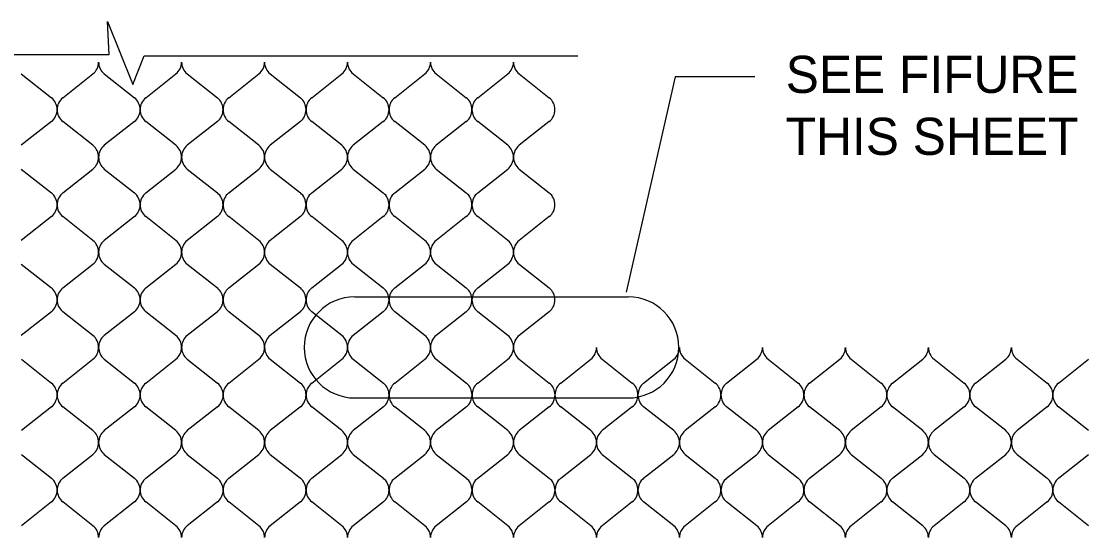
# Model space of a CAD drawing. Extents: x 638850 to 644908, y 297188 to 298900.
# Drawn here: x 640795.8 to 640882, y 298180.3 to 298222 of the extents above; entities that cross this region are included whole.
import ezdxf

# ---------------------------------------------------------------- set-up
doc = ezdxf.new("R2010")
doc.units = 0
for name, color, linetype in [('1', 7, 'Continuous'), ('2', 7, 'Continuous'), ('7', 7, 'Continuous')]:
    doc.layers.add(name, color=color, linetype=linetype)

msp = doc.modelspace()

# ---------------------------------------------------------------- linework, layer by layer
at = {"layer": '1'}
msp.add_line((640848.571, 298217.514), (640844.631, 298200.118), dxfattribs=at)
msp.add_lwpolyline([(640802.892, 298219.299), (640802.756, 298221.985), (640804.794, 298216.888), (640805.72, 298219.205)], dxfattribs=at)
for centre, start, end in [((640822.714, 298195.671), 90, 270), ((640844.797, 298195.671), 270, 90)]:
    msp.add_arc(centre, 4.078, start, end, dxfattribs=at)
at = {"layer": '2'}
for p, q in [((640795.796, 298217.737), (640798.228, 298215.819)), ((640799.147, 298215.819), (640801.579, 298217.737)), ((640802.497, 298217.737), (640804.929, 298215.819)), ((640805.845, 298215.819), (640808.277, 298217.737)), ((640809.195, 298217.737), (640811.627, 298215.819)), ((640812.541, 298215.819), (640814.973, 298217.737)), ((640815.891, 298217.737), (640818.323, 298215.819)), ((640819.239, 298215.819), (640821.671, 298217.737)), ((640822.589, 298217.737), (640825.021, 298215.819)), ((640825.94, 298215.819), (640828.372, 298217.737)), ((640829.29, 298217.737), (640831.722, 298215.819)), ((640832.638, 298215.819), (640835.07, 298217.737)), ((640835.988, 298217.737), (640838.42, 298215.819)), ((640798.228, 298213.899), (640795.796, 298211.98)), ((640801.579, 298211.98), (640799.147, 298213.899)), ((640804.929, 298213.899), (640802.497, 298211.98)), ((640808.277, 298211.98), (640805.845, 298213.899)), ((640811.627, 298213.899), (640809.195, 298211.98)), ((640814.973, 298211.98), (640812.541, 298213.899)), ((640818.323, 298213.899), (640815.891, 298211.98)), ((640821.671, 298211.98), (640819.239, 298213.899)), ((640825.021, 298213.899), (640822.589, 298211.98)), ((640828.372, 298211.98), (640825.94, 298213.899)), ((640831.722, 298213.899), (640829.29, 298211.98)), ((640835.07, 298211.98), (640832.638, 298213.899)), ((640838.42, 298213.899), (640835.988, 298211.98)), ((640795.796, 298210.062), (640798.228, 298208.144)), ((640799.147, 298208.144), (640801.579, 298210.062)), ((640802.497, 298210.062), (640804.929, 298208.144)), ((640805.845, 298208.144), (640808.277, 298210.062)), ((640809.195, 298210.062), (640811.627, 298208.144)), ((640812.541, 298208.144), (640814.973, 298210.062)), ((640815.891, 298210.062), (640818.323, 298208.144)), ((640819.239, 298208.144), (640821.671, 298210.062)), ((640822.589, 298210.062), (640825.021, 298208.144)), ((640825.94, 298208.144), (640828.372, 298210.062)), ((640829.29, 298210.062), (640831.722, 298208.144)), ((640832.638, 298208.144), (640835.07, 298210.062)), ((640835.988, 298210.062), (640838.42, 298208.144)), ((640798.228, 298206.224), (640795.796, 298204.306)), ((640801.579, 298204.306), (640799.147, 298206.224)), ((640804.929, 298206.224), (640802.497, 298204.306)), ((640808.277, 298204.306), (640805.845, 298206.224)), ((640811.627, 298206.224), (640809.195, 298204.306)), ((640814.973, 298204.306), (640812.541, 298206.224)), ((640818.323, 298206.224), (640815.891, 298204.306)), ((640821.671, 298204.306), (640819.239, 298206.224)), ((640825.021, 298206.224), (640822.589, 298204.306)), ((640828.372, 298204.306), (640825.94, 298206.224)), ((640831.722, 298206.224), (640829.29, 298204.306)), ((640835.07, 298204.306), (640832.638, 298206.224)), ((640838.42, 298206.224), (640835.988, 298204.306)), ((640795.796, 298202.388), (640798.228, 298200.469)), ((640799.147, 298200.469), (640801.579, 298202.388)), ((640802.497, 298202.388), (640804.929, 298200.469)), ((640805.845, 298200.469), (640808.277, 298202.388)), ((640809.195, 298202.388), (640811.627, 298200.469)), ((640812.541, 298200.469), (640814.973, 298202.388)), ((640815.891, 298202.388), (640818.323, 298200.469)), ((640819.239, 298200.469), (640821.671, 298202.388)), ((640822.589, 298202.388), (640825.021, 298200.469)), ((640825.94, 298200.469), (640828.372, 298202.388)), ((640829.29, 298202.388), (640831.722, 298200.469)), ((640832.638, 298200.469), (640835.07, 298202.388)), ((640835.988, 298202.388), (640838.42, 298200.469)), ((640798.228, 298198.549), (640795.796, 298196.631)), ((640801.579, 298196.631), (640799.147, 298198.549)), ((640804.929, 298198.549), (640802.497, 298196.631)), ((640808.277, 298196.631), (640805.845, 298198.549)), ((640811.627, 298198.549), (640809.195, 298196.631)), ((640814.973, 298196.631), (640812.541, 298198.549)), ((640818.323, 298198.549), (640815.891, 298196.631)), ((640821.671, 298196.631), (640819.239, 298198.549)), ((640825.021, 298198.549), (640822.589, 298196.631)), ((640828.372, 298196.631), (640825.94, 298198.549)), ((640831.722, 298198.549), (640829.29, 298196.631)), ((640835.07, 298196.631), (640832.638, 298198.549)), ((640838.42, 298198.549), (640835.988, 298196.631)), ((640795.801, 298194.711), (640798.233, 298192.792)), ((640799.149, 298192.792), (640801.581, 298194.711)), ((640802.499, 298194.711), (640804.931, 298192.792)), ((640805.847, 298192.792), (640808.279, 298194.711)), ((640809.197, 298194.711), (640811.629, 298192.792)), ((640812.545, 298192.792), (640814.978, 298194.711)), ((640815.895, 298194.711), (640818.327, 298192.792)), ((640819.244, 298192.792), (640821.676, 298194.711)), ((640822.594, 298194.711), (640825.026, 298192.792)), ((640825.942, 298192.792), (640828.374, 298194.711)), ((640829.292, 298194.711), (640831.724, 298192.792)), ((640832.64, 298192.792), (640835.072, 298194.711)), ((640835.99, 298194.711), (640838.422, 298192.792)), ((640839.338, 298192.792), (640841.771, 298194.711)), ((640842.688, 298194.711), (640845.12, 298192.792)), ((640846.037, 298192.792), (640848.469, 298194.711)), ((640849.387, 298194.711), (640851.819, 298192.792)), ((640852.735, 298192.792), (640855.167, 298194.711)), ((640856.085, 298194.711), (640858.517, 298192.792)), ((640859.433, 298192.792), (640861.865, 298194.711)), ((640862.783, 298194.711), (640865.215, 298192.792)), ((640866.131, 298192.792), (640868.564, 298194.711)), ((640869.481, 298194.711), (640871.913, 298192.792)), ((640872.83, 298192.792), (640875.262, 298194.711)), ((640876.18, 298194.711), (640878.612, 298192.792)), ((640879.528, 298192.792), (640881.96, 298194.711)), ((640798.233, 298190.872), (640795.801, 298188.954)), ((640801.581, 298188.954), (640799.149, 298190.872)), ((640804.931, 298190.872), (640802.499, 298188.954)), ((640808.279, 298188.954), (640805.847, 298190.872)), ((640811.629, 298190.872), (640809.197, 298188.954)), ((640814.978, 298188.954), (640812.545, 298190.872)), ((640818.327, 298190.872), (640815.895, 298188.954)), ((640821.676, 298188.954), (640819.244, 298190.872)), ((640825.026, 298190.872), (640822.594, 298188.954)), ((640828.374, 298188.954), (640825.942, 298190.872)), ((640831.724, 298190.872), (640829.292, 298188.954)), ((640835.072, 298188.954), (640832.64, 298190.872)), ((640838.422, 298190.872), (640835.99, 298188.954)), ((640841.771, 298188.954), (640839.338, 298190.872)), ((640845.12, 298190.872), (640842.688, 298188.954)), ((640848.469, 298188.954), (640846.037, 298190.872)), ((640851.819, 298190.872), (640849.387, 298188.954)), ((640855.167, 298188.954), (640852.735, 298190.872)), ((640858.517, 298190.872), (640856.085, 298188.954)), ((640861.865, 298188.954), (640859.433, 298190.872)), ((640865.215, 298190.872), (640862.783, 298188.954)), ((640868.564, 298188.954), (640866.131, 298190.872)), ((640871.913, 298190.872), (640869.481, 298188.954)), ((640875.262, 298188.954), (640872.83, 298190.872)), ((640878.612, 298190.872), (640876.18, 298188.954)), ((640881.96, 298188.954), (640879.528, 298190.872)), ((640795.801, 298187.034), (640798.233, 298185.115)), ((640799.149, 298185.115), (640801.581, 298187.034)), ((640802.499, 298187.034), (640804.931, 298185.115)), ((640805.847, 298185.115), (640808.279, 298187.034)), ((640809.197, 298187.034), (640811.629, 298185.115)), ((640812.545, 298185.115), (640814.978, 298187.034)), ((640815.895, 298187.034), (640818.327, 298185.115)), ((640819.244, 298185.115), (640821.676, 298187.034)), ((640822.594, 298187.034), (640825.026, 298185.115)), ((640825.942, 298185.115), (640828.374, 298187.034)), ((640829.292, 298187.034), (640831.724, 298185.115)), ((640832.64, 298185.115), (640835.072, 298187.034)), ((640835.99, 298187.034), (640838.422, 298185.115)), ((640839.338, 298185.115), (640841.771, 298187.034)), ((640842.688, 298187.034), (640845.12, 298185.115)), ((640846.037, 298185.115), (640848.469, 298187.034)), ((640849.387, 298187.034), (640851.819, 298185.115)), ((640852.735, 298185.115), (640855.167, 298187.034)), ((640856.085, 298187.034), (640858.517, 298185.115)), ((640859.433, 298185.115), (640861.865, 298187.034)), ((640862.783, 298187.034), (640865.215, 298185.115)), ((640866.131, 298185.115), (640868.564, 298187.034)), ((640869.481, 298187.034), (640871.913, 298185.115)), ((640872.83, 298185.115), (640875.262, 298187.034)), ((640876.18, 298187.034), (640878.612, 298185.115)), ((640879.528, 298185.115), (640881.96, 298187.034)), ((640798.233, 298183.195), (640795.801, 298181.277)), ((640801.581, 298181.277), (640799.149, 298183.195)), ((640804.931, 298183.195), (640802.499, 298181.277)), ((640808.279, 298181.277), (640805.847, 298183.195)), ((640811.629, 298183.195), (640809.197, 298181.277)), ((640814.978, 298181.277), (640812.545, 298183.195)), ((640818.327, 298183.195), (640815.895, 298181.277)), ((640821.676, 298181.277), (640819.244, 298183.195)), ((640825.026, 298183.195), (640822.594, 298181.277)), ((640828.374, 298181.277), (640825.942, 298183.195)), ((640831.724, 298183.195), (640829.292, 298181.277)), ((640835.072, 298181.277), (640832.64, 298183.195)), ((640838.422, 298183.195), (640835.99, 298181.277)), ((640841.771, 298181.277), (640839.338, 298183.195)), ((640845.12, 298183.195), (640842.688, 298181.277)), ((640848.469, 298181.277), (640846.037, 298183.195)), ((640851.819, 298183.195), (640849.387, 298181.277)), ((640855.167, 298181.277), (640852.735, 298183.195)), ((640858.517, 298183.195), (640856.085, 298181.277)), ((640861.865, 298181.277), (640859.433, 298183.195)), ((640865.215, 298183.195), (640862.783, 298181.277)), ((640868.564, 298181.277), (640866.131, 298183.195)), ((640871.913, 298183.195), (640869.481, 298181.277)), ((640875.262, 298181.277), (640872.83, 298183.195)), ((640878.612, 298183.195), (640876.18, 298181.277)), ((640881.96, 298181.277), (640879.528, 298183.195))]:
    msp.add_line(p, q, dxfattribs=at)
for centre, start, end in [((640800.803, 298218.697), 308.94823, 0), ((640803.272, 298218.697), 180, 231.05177), ((640807.501, 298218.697), 308.94823, 0), ((640809.971, 298218.697), 180, 231.05177), ((640814.197, 298218.697), 308.94823, 0), ((640816.667, 298218.697), 180, 231.05177), ((640820.895, 298218.697), 308.94823, 0), ((640823.365, 298218.697), 180, 231.05177), ((640827.596, 298218.697), 308.94823, 0), ((640830.065, 298218.697), 180, 231.05177), ((640834.294, 298218.697), 308.94823, 0), ((640836.764, 298218.697), 180, 231.05177), ((640797.452, 298214.859), 0, 51.05177), ((640799.923, 298214.859), 128.94823, 180), ((640804.152, 298214.859), 0, 51.05177), ((640806.622, 298214.859), 128.94823, 180), ((640810.85, 298214.859), 0, 51.05177), ((640813.318, 298214.859), 128.94823, 180), ((640817.546, 298214.859), 0, 51.05177), ((640820.016, 298214.859), 128.94823, 180), ((640824.245, 298214.859), 0, 51.05177), ((640826.716, 298214.859), 128.94823, 180), ((640830.945, 298214.859), 0, 51.05177), ((640833.415, 298214.859), 128.94823, 180), ((640837.643, 298214.859), 0, 51.05177), ((640797.452, 298214.859), 308.94823, 0), ((640799.923, 298214.859), 180, 231.05177), ((640804.152, 298214.859), 308.94823, 0), ((640806.622, 298214.859), 180, 231.05177), ((640810.85, 298214.859), 308.94823, 0), ((640813.318, 298214.859), 180, 231.05177), ((640817.546, 298214.859), 308.94823, 0), ((640820.016, 298214.859), 180, 231.05177), ((640824.245, 298214.859), 308.94823, 0), ((640826.716, 298214.859), 180, 231.05177), ((640830.945, 298214.859), 308.94823, 0), ((640833.415, 298214.859), 180, 231.05177), ((640837.643, 298214.859), 308.94823, 0), ((640800.803, 298211.02), 0, 51.05177), ((640803.272, 298211.02), 128.94823, 180), ((640807.501, 298211.02), 0, 51.05177), ((640809.971, 298211.02), 128.94823, 180), ((640814.197, 298211.02), 0, 51.05177), ((640816.667, 298211.02), 128.94823, 180), ((640820.895, 298211.02), 0, 51.05177), ((640823.365, 298211.02), 128.94823, 180), ((640827.596, 298211.02), 0, 51.05177), ((640830.065, 298211.02), 128.94823, 180), ((640834.294, 298211.02), 0, 51.05177), ((640836.764, 298211.02), 128.94823, 180), ((640800.803, 298211.022), 308.94823, 0), ((640803.272, 298211.022), 180, 231.05177), ((640807.501, 298211.022), 308.94823, 0), ((640809.971, 298211.022), 180, 231.05177), ((640814.197, 298211.022), 308.94823, 0), ((640816.667, 298211.022), 180, 231.05177), ((640820.895, 298211.022), 308.94823, 0), ((640823.365, 298211.022), 180, 231.05177), ((640827.596, 298211.022), 308.94823, 0), ((640830.065, 298211.022), 180, 231.05177), ((640834.294, 298211.022), 308.94823, 0), ((640836.764, 298211.022), 180, 231.05177), ((640797.452, 298207.184), 0, 51.05177), ((640799.923, 298207.184), 128.94823, 180), ((640804.152, 298207.184), 0, 51.05177), ((640806.622, 298207.184), 128.94823, 180), ((640810.85, 298207.184), 0, 51.05177), ((640813.318, 298207.184), 128.94823, 180), ((640817.546, 298207.184), 0, 51.05177), ((640820.016, 298207.184), 128.94823, 180), ((640824.245, 298207.184), 0, 51.05177), ((640826.716, 298207.184), 128.94823, 180), ((640830.945, 298207.184), 0, 51.05177), ((640833.415, 298207.184), 128.94823, 180), ((640837.643, 298207.184), 0, 51.05177), ((640797.452, 298207.184), 308.94823, 0), ((640799.923, 298207.184), 180, 231.05177), ((640804.152, 298207.184), 308.94823, 0), ((640806.622, 298207.184), 180, 231.05177), ((640810.85, 298207.184), 308.94823, 0), ((640813.318, 298207.184), 180, 231.05177), ((640817.546, 298207.184), 308.94823, 0), ((640820.016, 298207.184), 180, 231.05177), ((640824.245, 298207.184), 308.94823, 0), ((640826.716, 298207.184), 180, 231.05177), ((640830.945, 298207.184), 308.94823, 0), ((640833.415, 298207.184), 180, 231.05177), ((640837.643, 298207.184), 308.94823, 0), ((640800.803, 298203.346), 0, 51.05177), ((640803.272, 298203.346), 128.94823, 180), ((640807.501, 298203.346), 0, 51.05177), ((640809.971, 298203.346), 128.94823, 180), ((640814.197, 298203.346), 0, 51.05177), ((640816.667, 298203.346), 128.94823, 180), ((640820.895, 298203.346), 0, 51.05177), ((640823.365, 298203.346), 128.94823, 180), ((640827.596, 298203.346), 0, 51.05177), ((640830.065, 298203.346), 128.94823, 180), ((640834.294, 298203.346), 0, 51.05177), ((640836.764, 298203.346), 128.94823, 180), ((640800.803, 298203.348), 308.94823, 0), ((640803.272, 298203.348), 180, 231.05177), ((640807.501, 298203.348), 308.94823, 0), ((640809.971, 298203.348), 180, 231.05177), ((640814.197, 298203.348), 308.94823, 0), ((640816.667, 298203.348), 180, 231.05177), ((640820.895, 298203.348), 308.94823, 0), ((640823.365, 298203.348), 180, 231.05177), ((640827.596, 298203.348), 308.94823, 0), ((640830.065, 298203.348), 180, 231.05177), ((640834.294, 298203.348), 308.94823, 0), ((640836.764, 298203.348), 180, 231.05177), ((640797.452, 298199.509), 0, 51.05177), ((640799.923, 298199.509), 128.94823, 180), ((640804.152, 298199.509), 0, 51.05177), ((640806.622, 298199.509), 128.94823, 180), ((640810.85, 298199.509), 0, 51.05177), ((640813.318, 298199.509), 128.94823, 180), ((640817.546, 298199.509), 0, 51.05177), ((640820.016, 298199.509), 128.94823, 180), ((640824.245, 298199.509), 0, 51.05177), ((640826.716, 298199.509), 128.94823, 180), ((640830.945, 298199.509), 0, 51.05177), ((640833.415, 298199.509), 128.94823, 180), ((640837.643, 298199.509), 0, 51.05177), ((640797.452, 298199.509), 308.94823, 0), ((640799.923, 298199.509), 180, 231.05177), ((640804.152, 298199.509), 308.94823, 0), ((640806.622, 298199.509), 180, 231.05177), ((640810.85, 298199.509), 308.94823, 0), ((640813.318, 298199.509), 180, 231.05177), ((640817.546, 298199.509), 308.94823, 0), ((640820.016, 298199.509), 180, 231.05177), ((640824.245, 298199.509), 308.94823, 0), ((640826.716, 298199.509), 180, 231.05177), ((640830.945, 298199.509), 308.94823, 0), ((640833.415, 298199.509), 180, 231.05177), ((640837.643, 298199.509), 308.94823, 0), ((640800.803, 298195.671), 0, 51.05177), ((640803.272, 298195.671), 128.94823, 180), ((640807.501, 298195.671), 0, 51.05177), ((640809.971, 298195.671), 128.94823, 180), ((640814.197, 298195.671), 0, 51.05177), ((640816.667, 298195.671), 128.94823, 180), ((640820.895, 298195.671), 0, 51.05177), ((640823.365, 298195.671), 128.94823, 180), ((640827.596, 298195.671), 0, 51.05177), ((640830.065, 298195.671), 128.94823, 180), ((640834.294, 298195.671), 0, 51.05177), ((640836.764, 298195.671), 128.94823, 180), ((640800.805, 298195.671), 308.94823, 0), ((640803.275, 298195.671), 180, 231.05177), ((640807.503, 298195.671), 308.94823, 0), ((640809.973, 298195.671), 180, 231.05177), ((640814.202, 298195.671), 308.94823, 0), ((640816.671, 298195.671), 180, 231.05177), ((640820.9, 298195.671), 308.94823, 0), ((640823.369, 298195.671), 180, 231.05177), ((640827.598, 298195.671), 308.94823, 0), ((640830.068, 298195.671), 180, 231.05177), ((640834.296, 298195.671), 308.94823, 0), ((640836.766, 298195.671), 180, 231.05177), ((640840.995, 298195.671), 308.94823, 0), ((640843.464, 298195.671), 180, 231.05177), ((640847.693, 298195.671), 308.94823, 0), ((640850.162, 298195.671), 180, 231.05177), ((640854.391, 298195.671), 308.94823, 0), ((640856.861, 298195.671), 180, 231.05177), ((640861.089, 298195.671), 308.94823, 0), ((640863.559, 298195.671), 180, 231.05177), ((640867.788, 298195.671), 308.94823, 0), ((640870.257, 298195.671), 180, 231.05177), ((640874.486, 298195.671), 308.94823, 0), ((640876.955, 298195.671), 180, 231.05177), ((640797.456, 298191.832), 0, 51.05177), ((640799.926, 298191.832), 128.94823, 180), ((640804.154, 298191.832), 0, 51.05177), ((640806.624, 298191.832), 128.94823, 180), ((640810.853, 298191.832), 0, 51.05177), ((640813.322, 298191.832), 128.94823, 180), ((640817.551, 298191.832), 0, 51.05177), ((640820.02, 298191.832), 128.94823, 180), ((640824.249, 298191.832), 0, 51.05177), ((640826.719, 298191.832), 128.94823, 180), ((640830.947, 298191.832), 0, 51.05177), ((640833.417, 298191.832), 128.94823, 180), ((640837.646, 298191.832), 0, 51.05177), ((640840.115, 298191.832), 128.94823, 180), ((640844.344, 298191.832), 0, 51.05177), ((640846.813, 298191.832), 128.94823, 180), ((640851.042, 298191.832), 0, 51.05177), ((640853.512, 298191.832), 128.94823, 180), ((640857.74, 298191.832), 0, 51.05177), ((640860.21, 298191.832), 128.94823, 180), ((640864.439, 298191.832), 0, 51.05177), ((640866.908, 298191.832), 128.94823, 180), ((640871.137, 298191.832), 0, 51.05177), ((640873.606, 298191.832), 128.94823, 180), ((640877.835, 298191.832), 0, 51.05177), ((640880.305, 298191.832), 128.94823, 180), ((640797.456, 298191.832), 308.94823, 0), ((640799.926, 298191.832), 180, 231.05177), ((640804.154, 298191.832), 308.94823, 0), ((640806.624, 298191.832), 180, 231.05177), ((640810.853, 298191.832), 308.94823, 0), ((640813.322, 298191.832), 180, 231.05177), ((640817.551, 298191.832), 308.94823, 0), ((640820.02, 298191.832), 180, 231.05177), ((640824.249, 298191.832), 308.94823, 0), ((640826.719, 298191.832), 180, 231.05177), ((640830.947, 298191.832), 308.94823, 0), ((640833.417, 298191.832), 180, 231.05177), ((640837.646, 298191.832), 308.94823, 0), ((640840.115, 298191.832), 180, 231.05177), ((640844.344, 298191.832), 308.94823, 0), ((640846.813, 298191.832), 180, 231.05177), ((640851.042, 298191.832), 308.94823, 0), ((640853.512, 298191.832), 180, 231.05177), ((640857.74, 298191.832), 308.94823, 0), ((640860.21, 298191.832), 180, 231.05177), ((640864.439, 298191.832), 308.94823, 0), ((640866.908, 298191.832), 180, 231.05177), ((640871.137, 298191.832), 308.94823, 0), ((640873.606, 298191.832), 180, 231.05177), ((640877.835, 298191.832), 308.94823, 0), ((640880.305, 298191.832), 180, 231.05177), ((640800.805, 298187.994), 0, 51.05177), ((640803.275, 298187.994), 128.94823, 180), ((640807.503, 298187.994), 0, 51.05177), ((640809.973, 298187.994), 128.94823, 180), ((640814.202, 298187.994), 0, 51.05177), ((640816.671, 298187.994), 128.94823, 180), ((640820.9, 298187.994), 0, 51.05177), ((640823.369, 298187.994), 128.94823, 180), ((640827.598, 298187.994), 0, 51.05177), ((640830.068, 298187.994), 128.94823, 180), ((640834.296, 298187.994), 0, 51.05177), ((640836.766, 298187.994), 128.94823, 180), ((640840.995, 298187.994), 0, 51.05177), ((640843.464, 298187.994), 128.94823, 180), ((640847.693, 298187.994), 0, 51.05177), ((640850.162, 298187.994), 128.94823, 180), ((640854.391, 298187.994), 0, 51.05177), ((640856.861, 298187.994), 128.94823, 180), ((640861.089, 298187.994), 0, 51.05177), ((640863.559, 298187.994), 128.94823, 180), ((640867.788, 298187.994), 0, 51.05177), ((640870.257, 298187.994), 128.94823, 180), ((640874.486, 298187.994), 0, 51.05177), ((640876.955, 298187.994), 128.94823, 180), ((640800.805, 298187.994), 308.94823, 0), ((640803.275, 298187.994), 180, 231.05177), ((640807.503, 298187.994), 308.94823, 0), ((640809.973, 298187.994), 180, 231.05177), ((640814.202, 298187.994), 308.94823, 0), ((640816.671, 298187.994), 180, 231.05177), ((640820.9, 298187.994), 308.94823, 0), ((640823.369, 298187.994), 180, 231.05177), ((640827.598, 298187.994), 308.94823, 0), ((640830.068, 298187.994), 180, 231.05177), ((640834.296, 298187.994), 308.94823, 0), ((640836.766, 298187.994), 180, 231.05177), ((640840.995, 298187.994), 308.94823, 0), ((640843.464, 298187.994), 180, 231.05177), ((640847.693, 298187.994), 308.94823, 0), ((640850.162, 298187.994), 180, 231.05177), ((640854.391, 298187.994), 308.94823, 0), ((640856.861, 298187.994), 180, 231.05177), ((640861.089, 298187.994), 308.94823, 0), ((640863.559, 298187.994), 180, 231.05177), ((640867.788, 298187.994), 308.94823, 0), ((640870.257, 298187.994), 180, 231.05177), ((640874.486, 298187.994), 308.94823, 0), ((640876.955, 298187.994), 180, 231.05177), ((640797.456, 298184.155), 0, 51.05177), ((640799.926, 298184.155), 128.94823, 180), ((640804.154, 298184.155), 0, 51.05177), ((640806.624, 298184.155), 128.94823, 180), ((640810.853, 298184.155), 0, 51.05177), ((640813.322, 298184.155), 128.94823, 180), ((640817.551, 298184.155), 0, 51.05177), ((640820.02, 298184.155), 128.94823, 180), ((640824.249, 298184.155), 0, 51.05177), ((640826.719, 298184.155), 128.94823, 180), ((640830.947, 298184.155), 0, 51.05177), ((640833.417, 298184.155), 128.94823, 180), ((640837.646, 298184.155), 0, 51.05177), ((640840.115, 298184.155), 128.94823, 180), ((640844.344, 298184.155), 0, 51.05177), ((640846.813, 298184.155), 128.94823, 180), ((640851.042, 298184.155), 0, 51.05177), ((640853.512, 298184.155), 128.94823, 180), ((640857.74, 298184.155), 0, 51.05177), ((640860.21, 298184.155), 128.94823, 180), ((640864.439, 298184.155), 0, 51.05177), ((640866.908, 298184.155), 128.94823, 180), ((640871.137, 298184.155), 0, 51.05177), ((640873.606, 298184.155), 128.94823, 180), ((640877.835, 298184.155), 0, 51.05177), ((640880.305, 298184.155), 128.94823, 180), ((640797.456, 298184.155), 308.94823, 0), ((640799.926, 298184.155), 180, 231.05177), ((640804.154, 298184.155), 308.94823, 0), ((640806.624, 298184.155), 180, 231.05177), ((640810.853, 298184.155), 308.94823, 0), ((640813.322, 298184.155), 180, 231.05177), ((640817.551, 298184.155), 308.94823, 0), ((640820.02, 298184.155), 180, 231.05177), ((640824.249, 298184.155), 308.94823, 0), ((640826.719, 298184.155), 180, 231.05177), ((640830.947, 298184.155), 308.94823, 0), ((640833.417, 298184.155), 180, 231.05177), ((640837.646, 298184.155), 308.94823, 0), ((640840.115, 298184.155), 180, 231.05177), ((640844.344, 298184.155), 308.94823, 0), ((640846.813, 298184.155), 180, 231.05177), ((640851.042, 298184.155), 308.94823, 0), ((640853.512, 298184.155), 180, 231.05177), ((640857.74, 298184.155), 308.94823, 0), ((640860.21, 298184.155), 180, 231.05177), ((640864.439, 298184.155), 308.94823, 0), ((640866.908, 298184.155), 180, 231.05177), ((640871.137, 298184.155), 308.94823, 0), ((640873.606, 298184.155), 180, 231.05177), ((640877.835, 298184.155), 308.94823, 0), ((640880.305, 298184.155), 180, 231.05177), ((640800.805, 298180.317), 0, 51.05177), ((640803.275, 298180.317), 128.94823, 180), ((640807.503, 298180.317), 0, 51.05177), ((640809.973, 298180.317), 128.94823, 180), ((640814.202, 298180.317), 0, 51.05177), ((640816.671, 298180.317), 128.94823, 180), ((640820.9, 298180.317), 0, 51.05177), ((640823.369, 298180.317), 128.94823, 180), ((640827.598, 298180.317), 0, 51.05177), ((640830.068, 298180.317), 128.94823, 180), ((640834.296, 298180.317), 0, 51.05177), ((640836.766, 298180.317), 128.94823, 180), ((640840.995, 298180.317), 0, 51.05177), ((640843.464, 298180.317), 128.94823, 180), ((640847.693, 298180.317), 0, 51.05177), ((640850.162, 298180.317), 128.94823, 180), ((640854.391, 298180.317), 0, 51.05177), ((640856.861, 298180.317), 128.94823, 180), ((640861.089, 298180.317), 0, 51.05177), ((640863.559, 298180.317), 128.94823, 180), ((640867.788, 298180.317), 0, 51.05177), ((640870.257, 298180.317), 128.94823, 180), ((640874.486, 298180.317), 0, 51.05177), ((640876.955, 298180.317), 128.94823, 180)]:
    msp.add_arc(centre, 1.235, start, end, dxfattribs=at)
at = {"layer": '7'}
for p, q in [((640760.754, 298219.299), (640802.892, 298219.299)), ((640805.72, 298219.205), (640840.725, 298219.205)), ((640855.004, 298217.514), (640848.571, 298217.514)), ((640822.714, 298199.748), (640844.797, 298199.748)), ((640822.714, 298191.593), (640844.797, 298191.593))]:
    msp.add_line(p, q, dxfattribs=at)

# ---------------------------------------------------------------- texts
at = {"layer": '1'}
for s, p in [('SEE FIFURE B,', (640857.504, 298216.208)), ('THIS SHEET', (640857.504, 298211.208))]:
    msp.add_text(s, height=3, dxfattribs=at).set_placement(p)

doc.saveas('drawing.dxf')
